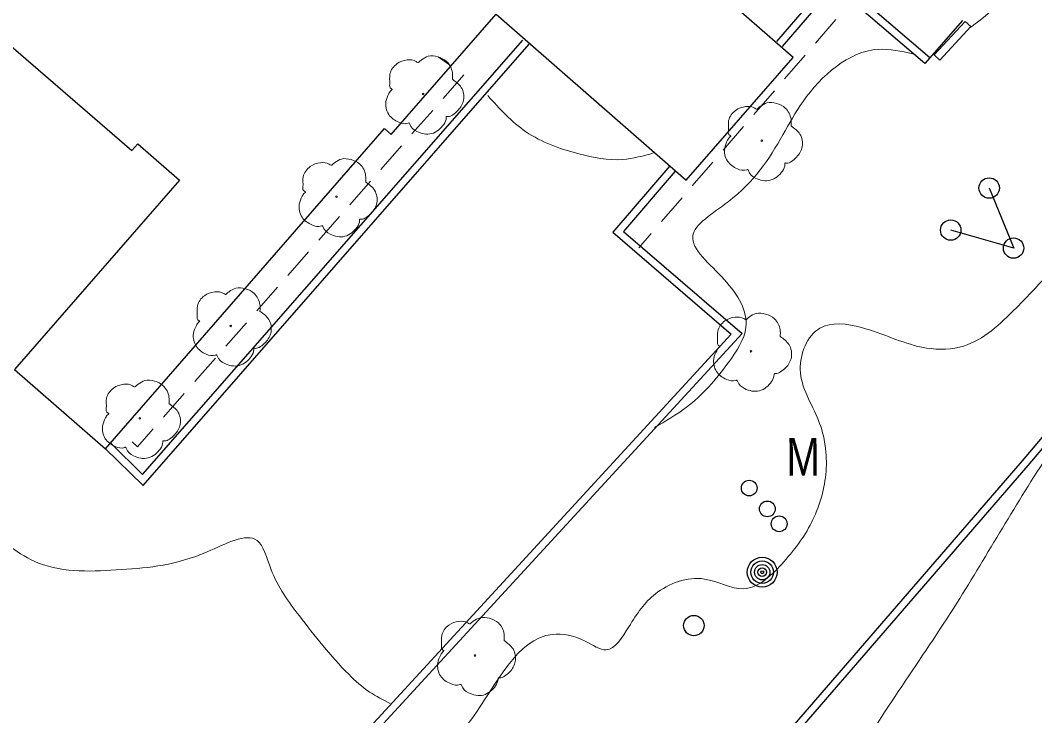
# Model space of a CAD drawing. Extents: x 2361708 to 2370558, y 6977955 to 6991887.
# Drawn here: x 2368666.6 to 2368795.7, y 6990345.6 to 6990434.2 of the extents above; entities that cross this region are included whole.
import ezdxf

# ---------------------------------------------------------------- set-up
doc = ezdxf.new("R2010")
doc.units = 0
doc.header["$LTSCALE"] = 1.9
for name, color, linetype, lineweight in [('11', 7, 'Continuous', 25), ('13', 7, 'Continuous', 13), ('2', 7, 'Continuous', 25), ('20', 7, 'Continuous', 25), ('21', 7, 'Continuous', 25), ('23', 7, 'Continuous', 25), ('29', 7, 'Continuous', 13), ('35', 7, 'Continuous', 13)]:
    doc.layers.add(name, color=color, linetype=linetype, lineweight=lineweight)

msp = doc.modelspace()

# ---------------------------------------------------------------- linework, layer by layer
at = {"layer": '11'}
msp.add_lwpolyline([(2368706.996, 6990535.603), (2368638.297, 6990456.356), (2368654.119, 6990442.636), (2368653.159, 6990441.537), (2368680.829, 6990417.559), (2368681.571, 6990418.406), (2368686.875, 6990413.786), (2368665.874, 6990389.665), (2368677.46, 6990379.585), (2368712.974, 6990420.375), (2368713.831, 6990419.623), (2368727.186, 6990434.921), (2368751.368, 6990413.81), (2368764.99, 6990429.41), (2368740.919, 6990450.423), (2368754.205, 6990465.65), (2368751.28, 6990468.202), (2368765.486, 6990484.458), (2368750.47, 6990497.575), (2368751.984, 6990499.31), (2368724.121, 6990523.666), (2368722.627, 6990521.962)], close=True, dxfattribs=at)
at = {"layer": '13'}
for p, q in [((2368770.434, 6990434.253), (2368767.823, 6990431.228)), ((2368719.797, 6990429.5), (2368721.428, 6990428.346)), ((2368766.517, 6990429.715), (2368763.906, 6990426.69)), ((2368762.6, 6990425.177), (2368759.989, 6990422.153)), ((2368719.122, 6990422.684), (2368716.48, 6990419.678)), ((2368758.683, 6990420.64), (2368756.072, 6990417.615)), ((2368715.165, 6990418.176), (2368712.523, 6990415.17)), ((2368754.766, 6990416.103), (2368752.155, 6990413.068)), ((2368711.207, 6990413.668), (2368708.576, 6990410.662)), ((2368750.849, 6990411.555), (2368748.238, 6990408.52)), ((2368707.26, 6990409.16), (2368704.619, 6990406.155)), ((2368746.933, 6990407.008), (2368745.35, 6990405.172)), ((2368703.303, 6990404.652), (2368700.671, 6990401.647)), ((2368699.356, 6990400.144), (2368696.724, 6990397.139)), ((2368695.408, 6990395.637), (2368692.767, 6990392.631)), ((2368691.451, 6990391.128), (2368688.819, 6990388.123)), ((2368687.503, 6990386.621), (2368684.872, 6990383.616))]:
    msp.add_line(p, q, dxfattribs=at)
for points in [[(2368723.059, 6990427.191), (2368723.069, 6990427.191), (2368720.438, 6990424.186)], [(2368683.557, 6990382.113), (2368681.548, 6990379.824), (2368680.852, 6990380.477)]]:
    msp.add_lwpolyline(points, dxfattribs=at)
at = {"layer": '2'}
for p, q in [((2368786.567, 6990434.136), (2368781.768, 6990428.66)), ((2368786.887, 6990434.009), (2368782.938, 6990429.751)), ((2368787.593, 6990433.356), (2368783.644, 6990429.098)), ((2368786.887, 6990434.009), (2368787.593, 6990433.356)), ((2368782.938, 6990429.751), (2368783.644, 6990429.098))]:
    msp.add_line(p, q, dxfattribs=at)
for points in [[(2368717.185, 6990288.919), (2368794.17, 6990378.056), (2368874.182, 6990472.802)], [(2368717.911, 6990288.296), (2368794.897, 6990377.433), (2368874.918, 6990472.179)], [(2368782.391, 6990429.386), (2368770.131, 6990439.92), (2368762.861, 6990431.45)], [(2368781.768, 6990428.66), (2368770.234, 6990438.561), (2368763.607, 6990430.837)], [(2368678.134, 6990380.271), (2368682.192, 6990376.29), (2368730.587, 6990431.643)], [(2368677.46, 6990379.585), (2368682.245, 6990374.89), (2368731.412, 6990431.131)], [(2368749.977, 6990414.937), (2368743.39, 6990407.264), (2368758.505, 6990394.247), (2368685.111, 6990314.375), (2368672.885, 6990325.479)], [(2368749.291, 6990415.611), (2368742.041, 6990407.161), (2368757.125, 6990394.164), (2368685.048, 6990315.724), (2368673.528, 6990326.185)]]:
    msp.add_lwpolyline(points, dxfattribs=at)
at = {"layer": '20'}
for centre, radius in [((2368759.402, 6990374.565), 1), ((2368761.707, 6990371.916), 1), ((2368763.215, 6990370.011), 1), ((2368761.054, 6990363.85), 1.9), ((2368761.054, 6990363.85), 1.442), ((2368761.054, 6990363.85), 0.973), ((2368761.054, 6990363.85), 0.539), ((2368761.054, 6990363.85), 0.192)]:
    msp.add_circle(centre, radius, dxfattribs=at)
at = {"layer": '21'}
for p, q in [((2368789.929, 6990412.797), (2368793.062, 6990405.146)), ((2368793.062, 6990405.146), (2368785.06, 6990407.44))]:
    msp.add_line(p, q, dxfattribs=at)
for centre in [(2368789.943, 6990412.792), (2368785.048, 6990407.434), (2368793.05, 6990405.14)]:
    msp.add_circle(centre, 1.3, dxfattribs=at)
at = {"layer": '23'}
msp.add_circle((2368752.358, 6990357.047), 1.3, dxfattribs=at)
at = {"layer": '29'}
for centre in [(2368717.902, 6990424.762), (2368761.011, 6990418.822), (2368706.866, 6990411.676), (2368693.402, 6990395.217), (2368759.626, 6990391.998), (2368681.834, 6990383.447), (2368724.493, 6990353.241)]:
    msp.add_circle(centre, 0.1, dxfattribs=at)
for points in [[(2368713.936, 6990425.334), (2368713.956, 6990425.344), (2368713.876, 6990425.414), (2368713.64, 6990426.041), (2368713.678, 6990427.322), (2368714.565, 6990428.62), (2368715.871, 6990429.103), (2368716.992, 6990428.914), (2368717.223, 6990428.786), (2368717.294, 6990428.786), (2368717.343, 6990428.827), (2368717.691, 6990429.12), (2368718.557, 6990429.569), (2368719.767, 6990429.5), (2368720.883, 6990428.911), (2368721.616, 6990427.488), (2368721.624, 6990426.628)], [(2368721.615, 6990426.647), (2368722.755, 6990425.588), (2368723.04, 6990424.001), (2368722.332, 6990422.674), (2368721.678, 6990422.128), (2368721.01, 6990421.911), (2368720.859, 6990421.9), (2368720.841, 6990421.79), (2368720.519, 6990420.887), (2368718.98, 6990419.722), (2368717.087, 6990420.004), (2368716.188, 6990420.946), (2368716.117, 6990421.075), (2368715.997, 6990421.054), (2368714.786, 6990421.173), (2368713.517, 6990422.17), (2368713.171, 6990423.807), (2368713.541, 6990424.83), (2368713.867, 6990425.274), (2368713.936, 6990425.324)], [(2368757.045, 6990419.394), (2368757.065, 6990419.405), (2368756.985, 6990419.474), (2368756.749, 6990420.101), (2368756.786, 6990421.382), (2368757.674, 6990422.68), (2368758.979, 6990423.163), (2368760.101, 6990422.973), (2368760.332, 6990422.846), (2368760.402, 6990422.846), (2368760.452, 6990422.887), (2368760.799, 6990423.18), (2368761.665, 6990423.629), (2368762.876, 6990423.56), (2368763.991, 6990422.97), (2368764.725, 6990421.548), (2368764.733, 6990420.688)], [(2368764.723, 6990420.708), (2368765.863, 6990419.648), (2368766.148, 6990418.061), (2368765.441, 6990416.734), (2368764.786, 6990416.188), (2368764.118, 6990415.971), (2368763.968, 6990415.96), (2368763.949, 6990415.85), (2368763.628, 6990414.947), (2368762.089, 6990413.782), (2368760.196, 6990414.064), (2368759.297, 6990415.006), (2368759.226, 6990415.135), (2368759.106, 6990415.114), (2368757.895, 6990415.232), (2368756.625, 6990416.23), (2368756.279, 6990417.867), (2368756.65, 6990418.89), (2368756.976, 6990419.334), (2368757.045, 6990419.384)], [(2368702.9, 6990412.249), (2368702.92, 6990412.259), (2368702.84, 6990412.328), (2368702.603, 6990412.956), (2368702.641, 6990414.236), (2368703.53, 6990415.535), (2368704.835, 6990416.017), (2368705.957, 6990415.828), (2368706.188, 6990415.7), (2368706.258, 6990415.701), (2368706.307, 6990415.741), (2368706.655, 6990416.034), (2368707.52, 6990416.483), (2368708.731, 6990416.414), (2368709.847, 6990415.825), (2368710.581, 6990414.402), (2368710.589, 6990413.542)], [(2368710.578, 6990413.562), (2368711.719, 6990412.502), (2368712.004, 6990410.915), (2368711.296, 6990409.589), (2368710.641, 6990409.042), (2368709.973, 6990408.826), (2368709.824, 6990408.814), (2368709.805, 6990408.704), (2368709.483, 6990407.801), (2368707.944, 6990406.637), (2368706.052, 6990406.918), (2368705.153, 6990407.86), (2368705.081, 6990407.989), (2368704.961, 6990407.968), (2368703.75, 6990408.087), (2368702.481, 6990409.085), (2368702.135, 6990410.721), (2368702.505, 6990411.745), (2368702.831, 6990412.188), (2368702.9, 6990412.239)], [(2368689.437, 6990395.79), (2368689.456, 6990395.8), (2368689.376, 6990395.869), (2368689.14, 6990396.497), (2368689.178, 6990397.777), (2368690.065, 6990399.076), (2368691.371, 6990399.558), (2368692.493, 6990399.369), (2368692.724, 6990399.241), (2368692.794, 6990399.242), (2368692.844, 6990399.283), (2368693.191, 6990399.576), (2368694.056, 6990400.024), (2368695.267, 6990399.955), (2368696.383, 6990399.366), (2368697.117, 6990397.943), (2368697.125, 6990397.083)], [(2368697.115, 6990397.103), (2368698.254, 6990396.043), (2368698.54, 6990394.456), (2368697.832, 6990393.13), (2368697.178, 6990392.583), (2368696.51, 6990392.367), (2368696.36, 6990392.356), (2368696.341, 6990392.245), (2368696.019, 6990391.342), (2368694.48, 6990390.177), (2368692.587, 6990390.459), (2368691.688, 6990391.401), (2368691.617, 6990391.53), (2368691.497, 6990391.509), (2368690.286, 6990391.628), (2368689.017, 6990392.626), (2368688.671, 6990394.262), (2368689.041, 6990395.286), (2368689.367, 6990395.729), (2368689.437, 6990395.78)], [(2368755.66, 6990392.57), (2368755.68, 6990392.58), (2368755.6, 6990392.65), (2368755.364, 6990393.277), (2368755.402, 6990394.557), (2368756.289, 6990395.856), (2368757.594, 6990396.338), (2368758.716, 6990396.149), (2368758.947, 6990396.021), (2368759.017, 6990396.022), (2368759.067, 6990396.062), (2368759.415, 6990396.356), (2368760.28, 6990396.804), (2368761.491, 6990396.736), (2368762.607, 6990396.146), (2368763.341, 6990394.723), (2368763.349, 6990393.863)], [(2368763.338, 6990393.883), (2368764.478, 6990392.824), (2368764.763, 6990391.236), (2368764.056, 6990389.91), (2368763.401, 6990389.364), (2368762.733, 6990389.147), (2368762.584, 6990389.136), (2368762.565, 6990389.025), (2368762.243, 6990388.122), (2368760.704, 6990386.958), (2368758.811, 6990387.24), (2368757.912, 6990388.181), (2368757.841, 6990388.31), (2368757.721, 6990388.289), (2368756.51, 6990388.408), (2368755.241, 6990389.406), (2368754.895, 6990391.042), (2368755.265, 6990392.066), (2368755.591, 6990392.509), (2368755.66, 6990392.56)], [(2368677.868, 6990384.019), (2368677.888, 6990384.029), (2368677.807, 6990384.099), (2368677.571, 6990384.726), (2368677.609, 6990386.007), (2368678.497, 6990387.305), (2368679.802, 6990387.787), (2368680.924, 6990387.599), (2368681.155, 6990387.471), (2368681.225, 6990387.471), (2368681.275, 6990387.512), (2368681.622, 6990387.805), (2368682.488, 6990388.253), (2368683.699, 6990388.185), (2368684.814, 6990387.595), (2368685.548, 6990386.172), (2368685.556, 6990385.312)], [(2368685.546, 6990385.332), (2368686.686, 6990384.273), (2368686.971, 6990382.685), (2368686.264, 6990381.359), (2368685.609, 6990380.813), (2368684.941, 6990380.596), (2368684.791, 6990380.585), (2368684.772, 6990380.475), (2368684.451, 6990379.572), (2368682.912, 6990378.407), (2368681.019, 6990378.689), (2368680.12, 6990379.63), (2368680.048, 6990379.76), (2368679.929, 6990379.739), (2368678.718, 6990379.857), (2368677.448, 6990380.855), (2368677.103, 6990382.492), (2368677.473, 6990383.515), (2368677.799, 6990383.958), (2368677.868, 6990384.009)], [(2368720.528, 6990353.813), (2368720.547, 6990353.824), (2368720.467, 6990353.893), (2368720.231, 6990354.52), (2368720.269, 6990355.802), (2368721.156, 6990357.1), (2368722.462, 6990357.582), (2368723.583, 6990357.393), (2368723.815, 6990357.265), (2368723.885, 6990357.266), (2368723.934, 6990357.306), (2368724.282, 6990357.6), (2368725.148, 6990358.048), (2368726.358, 6990357.979), (2368727.474, 6990357.39), (2368728.207, 6990355.967), (2368728.216, 6990355.107)], [(2368728.206, 6990355.127), (2368729.346, 6990354.067), (2368729.631, 6990352.48), (2368728.923, 6990351.153), (2368728.269, 6990350.607), (2368727.6, 6990350.391), (2368727.45, 6990350.379), (2368727.431, 6990350.27), (2368727.111, 6990349.366), (2368725.571, 6990348.201), (2368723.679, 6990348.484), (2368722.779, 6990349.425), (2368722.708, 6990349.554), (2368722.588, 6990349.533), (2368721.377, 6990349.652), (2368720.108, 6990350.649), (2368719.762, 6990352.286), (2368720.132, 6990353.31), (2368720.458, 6990353.753), (2368720.528, 6990353.804)]]:
    msp.add_spline(points, degree=3, dxfattribs=at)
at = {"layer": '35'}
for points in [[(2369047.828, 6990605.451), (2369038.394, 6990593.231), (2369027.418, 6990575.906), (2369015.841, 6990558.825), (2369000.65, 6990535.639), (2368993.146, 6990516.056), (2368986.096, 6990501.379), (2368978.606, 6990487.716), (2368969.405, 6990472.988), (2368958.108, 6990456.92), (2368955.454, 6990452.025), (2368953.073, 6990437.411), (2368952.752, 6990420.737), (2368959.614, 6990409.992), (2368963.269, 6990401.087), (2368969.023, 6990386.05), (2368979.207, 6990379.327), (2368988.134, 6990377.652), (2368992.144, 6990375.52), (2368991.785, 6990372.277), (2368987.467, 6990362.585), (2368986.816, 6990353.218), (2368988.815, 6990341.807), (2368989.62, 6990331.804), (2368986.922, 6990311.667), (2368979.307, 6990292.194), (2368965.455, 6990270.221), (2368943.017, 6990245.776), (2368913.099, 6990212.86), (2368880.694, 6990176.38), (2368844.682, 6990139.715), (2368811.712, 6990113.21), (2368778.447, 6990087.292), (2368739.578, 6990051.33), (2368711.829, 6990035.275), (2368686.864, 6990022.057), (2368673.109, 6990014.046), (2368669.745, 6990012.454), (2368668.706, 6990013.324), (2368669.63, 6990016.033), (2368674.153, 6990022.016), (2368684.646, 6990033.407), (2368697.173, 6990050.577), (2368697.763, 6990054.743), (2368695.615, 6990054.522), (2368688.933, 6990050.498), (2368671.541, 6990036.962), (2368648.494, 6990028.152), (2368625.507, 6990018.213), (2368603.069, 6990007.409), (2368581.573, 6989999.594), (2368572.511, 6989995.447), (2368567.234, 6989993.027)], [(2368983.929, 6990531.529), (2368979.435, 6990519.356), (2368975.701, 6990506), (2368972.153, 6990495.326), (2368965.023, 6990482.667), (2368952.28, 6990464.985), (2368944.692, 6990449.112), (2368936.279, 6990436.661), (2368930.708, 6990428.388), (2368926.974, 6990420.332), (2368923.178, 6990407.345), (2368925.818, 6990397.9), (2368929.492, 6990388.004), (2368932.253, 6990381.66), (2368935.154, 6990377.288), (2368935.872, 6990367.074), (2368936.658, 6990350.711), (2368934.899, 6990336.894), (2368925.545, 6990315.203), (2368919.061, 6990298.721), (2368917.665, 6990291.017), (2368922.007, 6990291.848), (2368928.932, 6990298.725), (2368940.303, 6990308.073), (2368954.807, 6990321.422), (2368956.934, 6990318.642), (2368952.658, 6990309.771), (2368947.879, 6990300.145), (2368939.818, 6990283.488), (2368927.075, 6990259.465), (2368910.767, 6990240.319), (2368886.835, 6990212.09), (2368866.726, 6990187.627), (2368845.138, 6990163.161), (2368822.496, 6990139.104), (2368799.648, 6990117.845), (2368778.178, 6990104.05), (2368756.592, 6990085.654), (2368734.588, 6990065.974), (2368713.09, 6990048.828), (2368704.692, 6990045.508), (2368705.15, 6990046.662), (2368709.481, 6990052.884), (2368718.059, 6990061.596), (2368727.733, 6990071.708), (2368736.854, 6990082.166), (2368748.659, 6990097.399), (2368759.795, 6990109.476), (2368764.382, 6990117.239), (2368763.943, 6990120.186), (2368757.319, 6990118.552), (2368746.862, 6990109.793), (2368726.432, 6990091.817), (2368699.934, 6990071.484), (2368679.435, 6990058.628), (2368654.88, 6990046.464), (2368626.237, 6990035.071), (2368603.78, 6990024.176), (2368586.487, 6990016.992), (2368573.437, 6990012.767), (2368565.504, 6990008.782), (2368560.239, 6990006.131), (2368556.575, 6990003.426)], [(2368853.291, 6990503.345), (2368849.094, 6990498.804), (2368839.887, 6990491.076), (2368830.71, 6990481.229), (2368823.089, 6990471.836), (2368814.315, 6990461.702), (2368811.494, 6990456.504), (2368813.214, 6990456.541), (2368824.116, 6990461.635), (2368829.313, 6990460.954), (2368828.341, 6990453.835), (2368821.215, 6990443.876), (2368815.415, 6990436.571), (2368809.217, 6990436.272), (2368805.138, 6990442.464), (2368804.463, 6990448.197), (2368796.985, 6990442.656), (2368788.012, 6990433.58), (2368787.525, 6990433.225)], [(2368306.448, 6990497.689), (2368306.381, 6990485.798), (2368306.875, 6990472.862), (2368314.304, 6990466.652), (2368320.698, 6990459.913), (2368328.691, 6990453.379), (2368336.59, 6990448.214), (2368336.349, 6990442.051), (2368329.045, 6990439.251), (2368323.69, 6990434.51), (2368320.725, 6990426.672), (2368318.707, 6990416.992), (2368317.476, 6990407.6), (2368316.021, 6990399.796), (2368315.408, 6990391.629), (2368317.477, 6990379.128), (2368321.246, 6990370.894), (2368327.763, 6990360.765), (2368332.504, 6990353.3), (2368336.691, 6990345.189), (2368342.784, 6990338.627), (2368352.452, 6990334.669), (2368363.488, 6990332.014), (2368372.052, 6990325.315), (2368384.563, 6990324.204), (2368392.56, 6990326.71), (2368402.723, 6990325.327), (2368407.846, 6990324.006), (2368422.852, 6990327.639), (2368438.688, 6990329.22), (2368451.482, 6990329.952), (2368466.361, 6990328.033), (2368482.419, 6990323.016), (2368493.157, 6990321.208), (2368501.477, 6990315.947), (2368510.222, 6990307.129), (2368523.896, 6990299.38), (2368536.862, 6990296.773), (2368546.63, 6990298.096), (2368556.237, 6990297.327), (2368560.836, 6990294.291), (2368565.853, 6990289.448), (2368566.111, 6990283.381), (2368566.362, 6990276.913), (2368567.176, 6990266.04), (2368565.907, 6990257.547), (2368568.272, 6990250.659), (2368572.868, 6990246.913), (2368578.046, 6990248.202), (2368585.128, 6990249.11), (2368588.446, 6990258.812), (2368586.77, 6990269.917), (2368591.867, 6990273.325), (2368601.012, 6990272.882), (2368610.964, 6990270.667), (2368622.374, 6990268.575), (2368629.997, 6990270.408), (2368635.673, 6990267.712), (2368641.529, 6990259.787), (2368648.359, 6990254.482), (2368652.762, 6990249.023), (2368658.453, 6990244.678), (2368661.468, 6990246.326), (2368666.518, 6990251.565), (2368673.531, 6990255.492), (2368677.989, 6990258.934), (2368680.855, 6990262.412), (2368681.559, 6990266.208), (2368681.94, 6990269.322), (2368682.334, 6990271.016)], [(2368789.929, 6990320.343), (2368790.53, 6990320.348), (2368797.873, 6990325.298), (2368807.423, 6990333.68), (2368817.733, 6990344.318), (2368829.52, 6990357.271), (2368840.79, 6990369.879), (2368857.89, 6990388.953), (2368868.503, 6990400.184), (2368882.774, 6990414.871), (2368900.904, 6990433.954), (2368914.357, 6990446.283), (2368927.592, 6990458.41), (2368938.738, 6990467.296), (2368945.543, 6990470.961), (2368944.236, 6990466.448), (2368939.885, 6990460.207), (2368933.405, 6990450.725), (2368923.326, 6990435.878), (2368917.886, 6990422.216), (2368911.041, 6990411.13), (2368905.079, 6990401.823), (2368900.974, 6990394.023), (2368900.322, 6990384.766), (2368901.314, 6990374.025), (2368904.437, 6990367.355), (2368904.31, 6990359.763), (2368903.563, 6990354.106), (2368901.129, 6990347.222), (2368896.475, 6990339.217), (2368894.175, 6990318.195), (2368888.579, 6990298.791), (2368874.725, 6990269.767), (2368859.183, 6990244.758), (2368839.662, 6990217.401), (2368811.187, 6990186.269), (2368782.802, 6990157.217), (2368754.567, 6990130.256), (2368727.088, 6990107.924), (2368698.455, 6990089.211), (2368672.208, 6990074.11), (2368648.698, 6990060.265), (2368628.721, 6990050.445), (2368613.068, 6990044.306), (2368603.074, 6990040.52), (2368593.252, 6990034.387), (2368582.867, 6990026.477), (2368572.981, 6990018.563), (2368564.602, 6990014.263), (2368560.596, 6990012.755), (2368556.513, 6990009.896), (2368554.167, 6990007.363), (2368553.067, 6990006.373)], [(2368668.236, 6990322.184), (2368674.54, 6990317.624), (2368682.079, 6990311.465), (2368688.665, 6990311.909), (2368693.65, 6990317.666), (2368704.856, 6990325.583), (2368716.448, 6990336.934), (2368724.09, 6990345.187), (2368734.348, 6990355.925), (2368738.516, 6990355.075), (2368741.207, 6990353.96), (2368744.07, 6990356.878), (2368747.47, 6990361.1), (2368753.712, 6990362.98), (2368758.694, 6990361.737), (2368763.812, 6990365.176), (2368767.51, 6990370.542), (2368769.182, 6990376.708), (2368768.22, 6990383.179), (2368765.899, 6990389.667), (2368768.378, 6990394.931), (2368773.708, 6990395.012), (2368781.362, 6990392.515), (2368786.172, 6990392.511), (2368792.969, 6990397.095), (2368801.23, 6990406.514), (2368807.472, 6990414.794), (2368815.842, 6990422.124), (2368824.626, 6990426.918), (2368831.332, 6990432.662), (2368838.086, 6990439.696), (2368844.131, 6990445.494), (2368850.602, 6990449.617), (2368855.66, 6990454.085), (2368862.375, 6990460.899), (2368866.547, 6990464.959), (2368870.217, 6990468.094)], [(2368672.622, 6990193.42), (2368677.499, 6990196.877), (2368689.448, 6990206.571), (2368704.224, 6990219.602), (2368717.195, 6990232.226), (2368732.475, 6990247.012), (2368743.676, 6990258.509), (2368759.297, 6990275.259), (2368769.621, 6990286.508), (2368783.909, 6990302.554), (2368801.545, 6990320.823), (2368816.251, 6990336.034), (2368827.604, 6990348.413), (2368841.891, 6990363.499), (2368853.954, 6990376.915), (2368873.879, 6990397.545), (2368883.733, 6990407.64), (2368895.263, 6990419.25), (2368903.392, 6990427.818), (2368912.434, 6990437.134)], [(2368780.236, 6990429.896), (2368775.821, 6990430.454), (2368766.263, 6990423.832), (2368763.694, 6990419.568), (2368756.724, 6990411.041), (2368752.216, 6990406.678), (2368756.229, 6990401.126), (2368758.977, 6990395.052), (2368756.74, 6990390.54), (2368751.433, 6990384.87), (2368747.338, 6990382.27)], [(2368726.115, 6990424.57), (2368730.988, 6990419.956), (2368737.726, 6990417.14), (2368743.302, 6990416.423), (2368747.225, 6990417.261)], [(2368804.747, 6990388.957), (2368797.543, 6990378.908), (2368785.823, 6990359.915), (2368772.025, 6990338.613), (2368760.005, 6990316.418), (2368745.29, 6990288.496), (2368744.177, 6990281.505), (2368744.733, 6990274.6), (2368746.231, 6990271.634)], [(2368655.892, 6990375.069), (2368662.062, 6990369.818), (2368668.959, 6990365.013), (2368679.477, 6990364.173), (2368690.426, 6990366.448), (2368696.763, 6990367.888), (2368698.517, 6990364.265), (2368702.144, 6990358.299), (2368708.425, 6990350.848), (2368711.087, 6990348.583), (2368713.721, 6990347.118)], [(2368639.713, 6990279.301), (2368639.624, 6990282.4), (2368637.263, 6990288.728), (2368631.445, 6990295.803), (2368619.919, 6990306.934), (2368607.196, 6990317.643), (2368601.222, 6990323.276), (2368595.469, 6990333.062), (2368596.967, 6990343.787), (2368597.188, 6990355.229), (2368600.34, 6990362.38), (2368607.993, 6990362.143), (2368614.065, 6990356.671), (2368622.165, 6990349.417), (2368629.941, 6990342.531), (2368638.606, 6990334.663), (2368646.718, 6990331.34), (2368654.451, 6990328.983), (2368659.909, 6990322.905), (2368662.814, 6990317.092), (2368668.189, 6990310.323), (2368674.893, 6990303.707), (2368680.8, 6990299.773), (2368686.756, 6990295.989), (2368693.452, 6990292.243), (2368694.523, 6990292.123), (2368695.323, 6990293.271)]]:
    msp.add_spline(points, degree=3, dxfattribs=at)

# ---------------------------------------------------------------- texts
at = {"layer": '20', "width": 0.8}
msp.add_text('M', height=4.8, rotation=0.545, dxfattribs=at).set_placement((2368764.148, 6990376.12))

doc.saveas('drawing.dxf')
